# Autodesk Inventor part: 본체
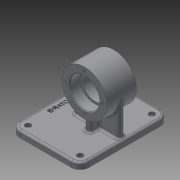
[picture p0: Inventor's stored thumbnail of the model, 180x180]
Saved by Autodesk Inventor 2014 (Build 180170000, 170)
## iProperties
Created: 2019-09
Part Number: 본체
Material: Generic
Document SubType Name: Modeling
Designer: kh
Density: 1 g/cm^3
Appearance: Default
Author: kh
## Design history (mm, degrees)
sketch "Sketch1"
  geometry: L1 (49, -63)-(-49, -63); L2 (-49, -63)-(-49, 63); L3 (-49, 63)-(49, 63); L4 (49, 63)-(49, -63); L5 (49, -63)-(-49, 63); L6 (-49, -63)-(49, 63); 1 further point
  constraints: 12 end point, 2 midpoint, 2 parallel, 1 horizontal, 1 perpendicular
  dimensions: "d0" = 98 distance of L2.end L3.end; "d1" = 126 distance of L1.end L2.end
extrude "Extrusion1" new body sketch "Sketch1" distance "d2" = 9; taper "d3" = 0 deg
workplane "Work Plane1"
sketch "Sketch2"
  geometry: L1 (-59, 42)-(-59, 84); L2 (0, 126)-(0, 0) reference; L3 (-59, 42)-(-91, 42); L4 (-91, 42)-(-91, 84); L5 (-91, 84)-(-59, 84); L6 (-91, 63)-(-59, 63); L7 (0, 126)-(-9, 126) reference; L8 (-80, 42)-(-80, 57); L9 (-80, 57)-(-77, 57); L10 (-77, 57)-(-77, 69); L11 (-77, 69)-(-80, 69); L12 (-80, 69)-(-80, 84); 1 further point
  constraints: 20 end point, 6 perpendicular, 2 midpoint, 2 parallel, 2 point on line, 1 vertical
  dimensions: "d5" = 59 distance between parallel lines of L2 L1; "d6" = 42 distance of L3.end L4.end; "d7" = 63 distance between parallel lines of L7 L6; "d8" = 64 diameter of L4 L1; "d9" = 42 diameter of L8 L1; "d10" = 36 diameter of L10 L1; "d11" = 42 diameter of L12 L1; "d12" = 15 distance of L8.start L8.end; "d13" = 15 distance of L11.end L12.end
revolve "Revolution1" sketch "Sketch2" stored, may be unused: angle "d14" = 90 deg
sketch "Sketch3"
  geometry: L1 (-49, 63)-(49, 63) reference; L2 (-49, -63)-(-49, 63) reference; L3 (-19, 4)-(45, 4); L4 (45, 4)-(45, -4); L5 (45, -4)-(-19, -4); L6 (-19, -4)-(-19, 4); L7 (-19, 4)-(45, -4); L8 (45, 4)-(-19, -4); L9 (17, 17)-(9, 17); L10 (9, 17)-(9, -17); L11 (9, -17)-(17, -17); L12 (17, -17)-(17, 17); L13 (17, 17)-(9, -17); L14 (9, 17)-(17, -17); 2 further points
  constraints: 24 end point, 4 midpoint, 4 parallel, 2 horizontal, 2 perpendicular
  dimensions: "d15" = 63 distance from line of L1 point (13, 0); "d16" = 62 distance from line of L2 point (13, 0); "d17" = 64 distance of L4.end L5.end; "d18" = 8 distance of L5.end L3.start; "d19" = 8 distance of L11.end L10.end; "d20" = 34 distance of L10.end L9.end
extrude "Extrusion2" join sketch "Sketch3" stored distance "d21" = 9; taper "d22" = 0 deg
fillet "Fillet1" dims "d23" = 12
fillet "Fillet2" dims "d24" = 3
fillet "Fillet3" dims "d25" = 3
fillet "Fillet4" dims "d26" = 3
chamfer "Chamfer1" distance "d27" = 1; stored, may be unused: second distance "d28" = 2, angle "d29" = 45 deg
fillet "Fillet5" dims "d30" = 0.3
sketch "Sketch4"
  geometry: C1 r 32 at (0, 0) reference; 2 further points
  constraints: 1 vertical alignment
  dimensions: "d31" = 26 distance of C1.centre point (0, 26)
hole "Hole1" sketch "Sketch4" at (0, 26) diameter "d32" = 3.242; stored, may be unused: countersink angle "d36" = 90 deg, drill point angle "d38" = 118 deg; dims "d33" = 8, "d34" = 4, "d35" = 2, "d37" = 10
pattern_circular "Circular Pattern1" dims angle "d40" = 360 deg
mirror "Mirror1"
hole "Hole2" diameter "d44" = 4.5; stored, may be unused: countersink angle "d48" = 90 deg, drill point angle "d50" = 118 deg; dims "d42" = 10, "d43" = 10, "d45" = 8, "d46" = 8, "d47" = 4.4, "d49" = 10
pattern_linear "Rectangular Pattern1" dims "d53" = 102, "d56" = 74
sketch "Sketch5"
  geometry: L1 (-42.002, -20.739)-(-42.002, 20.739); L2 (-42.002, 20.739)-(-35.998, 20.739); L3 (-35.998, 20.739)-(-35.998, -20.739); L4 (-35.998, -20.739)-(-42.002, -20.739); L5 (-42.002, -20.739)-(-35.998, 20.739); L6 (37, 63)-(-37, 63) reference; L7 (-49, 51)-(-49, -51) reference; 2 further points
  constraints: 2 end point, 1 midpoint, 2 other
  dimensions: "d57" = 63 distance from line of L6 point (-39, 0); "d58" = 10 distance from line of point (-39, 0) L7
emboss "Emboss1" sketch "Sketch5" dims "d5" = 59, "d6" = 42, "d7" = 63, "d8" = 64, "d9" = 42, "d10" = 36, "d11" = 42, "d12" = 15, "d13" = 15, "d59" = 0.5, "d60" = 0
body "Solid1"
other parameters: "d4" = -36
